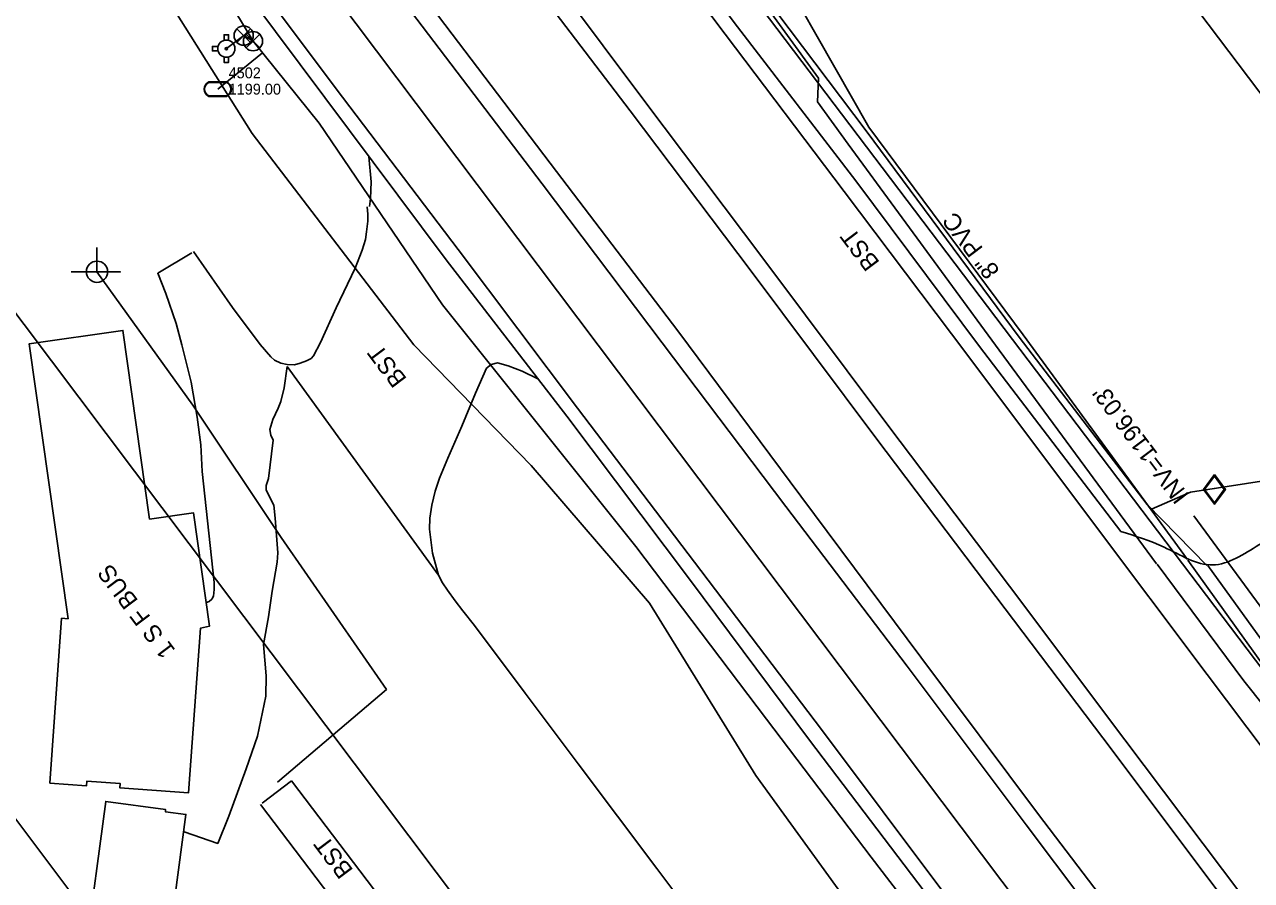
# Model space of a CAD drawing. Extents: x 1262092 to 1264624, y 774970 to 778314.
# Drawn here: x 1262721.5 to 1263004.7, y 777094.1 to 777291.5 of the extents above; entities that cross this region are included whole.
import ezdxf

# ---------------------------------------------------------------- set-up
doc = ezdxf.new("R2010")
doc.units = 0
for name, color, linetype in [('COGO Default Parcel', 7, 'Continuous'), ('Exist Boundary City Limits', 7, 'Continuous'), ('Exist Horizontal Alignment', 7, 'Continuous'), ('Exist Right of Way Line', 7, 'Continuous'), ('Exist Roads Curbs', 7, 'Continuous'), ('Exist Roads EOP', 7, 'Continuous'), ('Exist Roads EOP Other', 7, 'Continuous'), ('Exist Roads EOT', 7, 'Continuous'), ('Exist Structure Minor Pipes CMP 18 Inch', 7, 'Continuous'), ('Exist Structure Minor Pipes CMP 18 Inch Invert', 7, 'Continuous'), ('Exist Utilities Gas UG Line SUE LOS B', 7, 'Continuous'), ('Exist Utilities Gas Valve CELL', 7, 'Continuous'), ('Exist Utilities Power Joint Use Telephone CELL', 7, 'Continuous'), ('Exist Utilities Power UG Cable SUE LOS B', 7, 'Continuous'), ('Exist Utilities Sanitary Sewer UG Line', 7, 'Continuous'), ('Exist Utilities Sanitary Sewer UG Line Text', 7, 'Continuous'), ('Exist Utilities Telephone UG FO SUE LOS B', 7, 'Continuous'), ('Exist Utilities Water Fire Hydrant CELL', 7, 'Continuous'), ('Exist Utilities Water Meter CELL', 7, 'Continuous'), ('Exist Utilities Water Meter Cogo Elevation', 7, 'Continuous'), ('Exist Utilities Water Meter Cogo Number', 7, 'Continuous'), ('Exist Utilities Water UG Line SUE LOS B', 7, 'Continuous'), ('Exist Utilities Water Valve CELL', 7, 'Continuous'), ('Prop EOT', 7, 'Continuous'), ('Prop Horizontal Alignment', 7, 'Continuous'), ('Prop Horizontal Alignment Direction Label', 7, 'Continuous'), ('Prop Horizontal Alignment Tick Small', 7, 'Continuous'), ('Prop Shade Medium', 7, 'Continuous')]:
    doc.layers.add(name, color=color, linetype=linetype)

# ---------------------------------------------------------------- blocks, each defined once
blk = doc.blocks.new('EXIST UTILITIES WATER VALVE')
at = {"layer": 'Exist Utilities Water Valve CELL'}
blk.add_lwpolyline([(0.0315, 0.0315), (-0.0315, -0.0315), (0, 0), (0.0315, -0.0315), (-0.0315, 0.0315)], dxfattribs=at)
blk.add_circle((0, 0), 0.0445, dxfattribs=at)
blk = doc.blocks.new('EXIST UTILITIES WATER FIRE HYDRANT')
at = {"layer": 'Exist Utilities Water Fire Hydrant CELL'}
blk.add_line((0, 0), (0, 0), dxfattribs=at)
for points in [[(-0.01025, 0.03825), (-0.01025, 0.064), (0.01025, 0.064), (0.01025, 0.03775)], [(-0.03825, 0.01025), (-0.064, 0.01025), (-0.064, -0.01025), (-0.03825, -0.01025)], [(-0.01025, -0.03825), (-0.01025, -0.064), (0.01025, -0.064), (0.01025, -0.03775)]]:
    blk.add_lwpolyline(points, dxfattribs=at)
for radius in [0.03954, 0.00485]:
    blk.add_circle((0, 0), radius, dxfattribs=at)
blk = doc.blocks.new('EXIST UTILITIES WATER METER')
at = {"layer": 'Exist Utilities Water Meter CELL'}
blk.add_line((0, 0), (0, 0), dxfattribs=at)
for points in [[(-0.0408, 0.034), (0.0408, 0.034)], [(-0.0408, 0.0312), (0.0408, 0.0312)], [(0.0408, -0.0312), (-0.0413, -0.0312)], [(0.0408, -0.034), (-0.0413, -0.034)]]:
    blk.add_lwpolyline(points, dxfattribs=at)
for centre, radius, start, end in [((-0.0261, -0.0001), 0.0371, 113.178, 245.9794), ((-0.0259, -0.0001), 0.0347, 115.3009, 243.7824), ((0.0259, 0), 0.0371, 293.6483, 66.3084), ((0.0261, 0), 0.0345, 295.1272, 64.8728)]:
    blk.add_arc(centre, radius, start, end, dxfattribs=at)
blk = doc.blocks.new('EXIST UTILITIES GAS VALVE')
at = {"layer": 'Exist Utilities Gas Valve CELL'}
blk.add_line((0, 0), (0, 0), dxfattribs=at)
blk.add_lwpolyline([(0, 0.0683), (-0.0508, 0), (0, -0.0683), (0.0508, 0), (0, 0.0683)], dxfattribs=at)
blk.add_lwpolyline([(0.0458, 0), (0, 0.0615), (-0.0458, 0), (0, -0.0615)], close=True, dxfattribs=at)

msp = doc.modelspace()

# ---------------------------------------------------------------- linework, layer by layer
at = {"layer": 'COGO Default Parcel'}
msp.add_line((1263155.86, 776528.63), (1262121.77, 777902.18), dxfattribs=at)
at = {"layer": 'Exist Boundary City Limits'}
msp.add_line((1263013.39, 776834.66), (1262172.78, 777950.69), dxfattribs=at)
at = {"layer": 'Exist Horizontal Alignment'}
msp.add_line((1264460.35, 775084.79), (1262255.05, 778012.66), dxfattribs=at)
at = {"layer": 'Exist Right of Way Line'}
for p, q in [((1262380.46, 778107.12), (1263428.45, 776715.75)), ((1262172.78, 777950.69), (1263224.83, 776553.94))]:
    msp.add_line(p, q, dxfattribs=at)
at = {"layer": 'Exist Roads Curbs'}
for points in [[(1262760.55, 777239.15), (1262769.56, 777226.25), (1262775.93, 777217.68), (1262778.35, 777214.84), (1262779.26, 777214.07), (1262780.73, 777213.39), (1262782.18, 777213.1), (1262783.83, 777213.03), (1262785.17, 777213.37), (1262786.59, 777213.91), (1262787.69, 777214.47), (1262788.22, 777215.05), (1262789.86, 777218.13), (1262793.5, 777226.13), (1262797.82, 777235.3), (1262799.49, 777239.48), (1262800.23, 777241.93), (1262800.46, 777243.66), (1262800.79, 777246.14), (1262800.77, 777247.76), (1262800.62, 777249.46)], [(1262882.73, 777076.52), (1262867.45, 777096.86), (1262858.42, 777108.9), (1262849.34, 777120.99), (1262837.05, 777137.29), (1262825.37, 777152.88), (1262822.67, 777156.29), (1262820.95, 777158.53), (1262819.14, 777161.01), (1262818, 777162.68), (1262817.1, 777164.49), (1262815.71, 777169.58), (1262815.03, 777175.06), (1262815.09, 777177.66), (1262815.56, 777180.65), (1262816.32, 777183.82), (1262817.34, 777186.88), (1262819.23, 777191.45), (1262822.49, 777198.83), (1262825.63, 777206.45), (1262828.17, 777212.25)]]:
    msp.add_lwpolyline(points, dxfattribs=at)
at = {"layer": 'Exist Roads EOP'}
for p, q in [((1262817.1, 777164.49), (1262782.12, 777212.58)), ((1262776.39, 777111.88), (1262783.19, 777117.01))]:
    msp.add_line(p, q, dxfattribs=at)
for points in [[(1262982.53, 777073.82), (1262955.55, 777109.3), (1262928.42, 777145.56), (1262900.69, 777182.74), (1262872.34, 777220.82), (1262844.32, 777257.6), (1262815.63, 777295.35), (1262787.99, 777332.27), (1262760.77, 777368.27), (1262732.29, 777406.26), (1262703.53, 777444.22), (1262703.55, 777444.2), (1262675.64, 777481.25), (1262647.24, 777519.05), (1262619.25, 777556.57), (1262590.88, 777594.45), (1262562.41, 777631.96), (1262533.86, 777669.85), (1262506.16, 777706.68)], [(1262581.77, 777696.76), (1262605.02, 777665.12), (1262633.36, 777627.24), (1262661.91, 777589.34), (1262690.46, 777551.49), (1262719.22, 777513.4), (1262746.97, 777476.08), (1262773.62, 777440.76), (1262802.75, 777402.21), (1262831.32, 777364.09), (1262858.19, 777328.14), (1262886.09, 777290.94), (1262913.38, 777255.47), (1262941.92, 777217.23), (1262974.58, 777174.56)], [(1262930.86, 777089.4), (1262902.71, 777126.43), (1262875.01, 777163.54), (1262846.68, 777201.15), (1262818.83, 777237.2), (1262790.81, 777274.63), (1262762.38, 777312.81), (1262734.99, 777348.79), (1262707.23, 777385.88), (1262678.03, 777424.58), (1262678.1, 777424.6), (1262649.57, 777462.36), (1262621.56, 777499.63), (1262593.49, 777536.82), (1262564.97, 777574.69), (1262536.79, 777612.19), (1262508.59, 777649.5), (1262480.62, 777686.61)], [(1262551.17, 777683.56), (1262580.06, 777645.73), (1262608.84, 777607.53), (1262637.53, 777569.2), (1262664.94, 777532.66), (1262692.64, 777496.32), (1262720.62, 777458.91), (1262748.48, 777421.14), (1262777.36, 777382.85), (1262804.87, 777346.49), (1262832.58, 777309.22), (1262861.34, 777271.61), (1262889.26, 777234.57), (1262918.02, 777196.13), (1262945.71, 777159.53), (1262972.54, 777124.15), (1262999.26, 777088.5)], [(1262875.07, 776996.05), (1262783.19, 777117.01)], [(1262864.31, 776988.27), (1262843.08, 777016.06), (1262846.56, 777018.7), (1262776, 777111.59)]]:
    msp.add_lwpolyline(points, dxfattribs=at)
msp.add_spline([(1262974.58, 777174.56), (1262984.58, 777170.91), (1262995.75, 777166.84), (1263006.39, 777171.47), (1263014.57, 777176.38)], degree=3, dxfattribs=at)
at = {"layer": 'Exist Roads EOP Other'}
for points in [[(1262801.13, 777249.51), (1262801.38, 777251.38), (1262801.52, 777255.2), (1262800.98, 777261.04)], [(1262772.67, 777119.78), (1262775.32, 777127.37), (1262777.26, 777136.56), (1262777.31, 777141.28), (1262776.73, 777148.5), (1262777.88, 777154.84), (1262778.71, 777160.82), (1262779.83, 777167.49), (1262780.01, 777169.62), (1262779.42, 777177.62), (1262779.1, 777180.6), (1262777.3, 777184.08), (1262777.3, 777185.19), (1262777.82, 777186.81), (1262778.89, 777195.61), (1262778.42, 777196.77), (1262778.13, 777198.05), (1262778.88, 777200.42), (1262780.1, 777202.98), (1262780.71, 777204.54), (1262781.47, 777207.72), (1262782.12, 777212.58)], [(1262828.17, 777212.25), (1262829.24, 777213.08), (1262830.72, 777213.48), (1262833.12, 777212.8), (1262836.39, 777211.57), (1262840.01, 777209.77)], [(1262758.38, 777105.25), (1262766.15, 777102.61), (1262768.7, 777108.9), (1262772.67, 777119.78)]]:
    msp.add_lwpolyline(points, dxfattribs=at)
at = {"layer": 'Exist Roads EOT'}
for points in [[(1262979.34, 777071.55), (1262952.73, 777106.88), (1262925.27, 777143.52), (1262897.25, 777180.33), (1262868.7, 777218.05), (1262841.03, 777254.71), (1262812.09, 777292.76), (1262784.33, 777329.52), (1262756.93, 777366.26), (1262729.04, 777403.83), (1262700.43, 777442.05), (1262700.42, 777442.08), (1262672.68, 777478.81), (1262644.08, 777516.56), (1262615.98, 777553.77), (1262587.41, 777591.99), (1262558.81, 777629.41), (1262530.21, 777667.14), (1262502.53, 777703.54)], [(1262573.92, 777700.82), (1262602.3, 777663.12), (1262630.46, 777625.47), (1262658.86, 777587.71), (1262687.81, 777549.36), (1262715.91, 777512.01), (1262744.26, 777474.24), (1262770.57, 777439.41), (1262799.73, 777400.38), (1262828.22, 777362.56), (1262855.35, 777326.32), (1262883.21, 777289.28), (1262910.68, 777252.94), (1262938.99, 777215.45), (1262967.77, 777177.08), (1262994.46, 777141.54), (1263021.73, 777105.43)], [(1262933.46, 777091.49), (1262905.72, 777128.55), (1262877.63, 777165.57), (1262849.13, 777203), (1262821.64, 777239.58), (1262793.48, 777276.64), (1262765, 777314.68), (1262737.64, 777351.02), (1262709.57, 777388.53), (1262680.86, 777426.61), (1262652.4, 777464.54), (1262624.47, 777501.81), (1262596.33, 777538.99), (1262567.58, 777576.78), (1262539.34, 777614.06), (1262511.28, 777651.42), (1262483.32, 777688.89)], [(1262554.72, 777686.15), (1262583.3, 777648.11), (1262611.88, 777610.15), (1262640.7, 777571.7), (1262668.16, 777535.24), (1262695.77, 777498.64), (1262723.78, 777461.2), (1262751.96, 777423.82), (1262781.01, 777385.34), (1262781, 777385.31), (1262808.32, 777349.17), (1262836.1, 777312), (1262864.5, 777274.02), (1262892.16, 777237.27), (1262921.03, 777198.81), (1262948.88, 777161.95), (1262975.45, 777126.54), (1263002.46, 777090.67)]]:
    msp.add_lwpolyline(points, dxfattribs=at)
at = {"layer": 'Exist Structure Minor Pipes CMP 18 Inch'}
msp.add_line((1263026.59, 777130.21), (1262991.4, 777178.18), dxfattribs=at)
at = {"layer": 'Exist Utilities Gas UG Line SUE LOS B'}
for points in [[(1262994.39, 777166.73), (1262980.63, 777180.77), (1262951.12, 777219.34), (1262915.77, 777266.99), (1262883.3, 777310), (1262857.54, 777344.34), (1262828.14, 777381.91), (1262793.47, 777427.19), (1262760.54, 777472.85), (1262727.33, 777519.3), (1262694.08, 777555.83), (1262655.09, 777608.15), (1262623.1, 777653.3), (1262592.34, 777693.87), (1262575.48, 777722.21), (1262534.9, 777775.61), (1262497.72, 777820.92), (1262460.79, 777868.95), (1262430.33, 777909.82), (1262335.35, 778033.97), (1262366.66, 777994.16), (1262337.19, 778032.97), (1262314.26, 778062.88)], [(1262994.39, 777166.73), (1262980.63, 777180.77), (1262951.12, 777219.34), (1262915.77, 777266.99), (1262883.3, 777310), (1262857.54, 777344.34), (1262828.14, 777381.91), (1262793.47, 777427.19), (1262760.54, 777472.85), (1262727.33, 777519.3), (1262694.08, 777555.83), (1262655.09, 777608.15), (1262623.1, 777653.3), (1262592.34, 777693.87), (1262575.48, 777722.21), (1262534.9, 777775.61), (1262497.72, 777820.92), (1262460.79, 777868.95), (1262430.33, 777909.82), (1262335.35, 778033.97), (1262366.66, 777994.16), (1262337.19, 778032.97), (1262314.26, 778062.88)], [(1262981.64, 777179.74), (1262990.66, 777183.59), (1263010.03, 777186.59), (1263023.13, 777192.41), (1263060.72, 777217.64), (1263088.74, 777237.85)], [(1262981.64, 777179.74), (1262990.66, 777183.59), (1263010.03, 777186.59), (1263023.13, 777192.41), (1263060.72, 777217.64), (1263088.74, 777237.85)], [(1263356.42, 776704.29), (1263329.58, 776735.35), (1263277.38, 776797.97), (1263260.37, 776819.29), (1263232.35, 776857.44), (1263174.41, 776935.65), (1263134.72, 776985.69), (1263099.47, 777025.86), (1263058.51, 777081.95), (1263034.87, 777111.45), (1263010.04, 777145.44), (1262994.6, 777166.7)], [(1263356.42, 776704.29), (1263329.58, 776735.35), (1263277.38, 776797.97), (1263260.37, 776819.29), (1263232.35, 776857.44), (1263174.41, 776935.65), (1263134.72, 776985.69), (1263099.47, 777025.86), (1263058.51, 777081.95), (1263034.87, 777111.45), (1263010.04, 777145.44), (1262994.6, 777166.7)]]:
    msp.add_lwpolyline(points, dxfattribs=at)
at = {"layer": 'Exist Utilities Power Joint Use Telephone CELL'}
msp.add_line((1262738.26, 777234.45), (1262738.26, 777234.45), dxfattribs=at)
msp.add_lwpolyline([(1262732.32, 777234.45), (1262743.66, 777234.42), (1262738.26, 777234.43), (1262738.26, 777240.08)], dxfattribs=at)
msp.add_circle((1262738.26, 777234.46), 2.45, dxfattribs=at)
at = {"layer": 'Exist Utilities Power UG Cable SUE LOS B'}
msp.add_lwpolyline([(1262779.96, 777116.73), (1262805.07, 777138.14), (1262780.75, 777173.2), (1262760.4, 777203.7), (1262738.26, 777234.45)], dxfattribs=at)
at = {"layer": 'Exist Utilities Sanitary Sewer UG Line'}
msp.add_line((1263142.14, 776964.69), (1262537.27, 777762.91), dxfattribs=at)
at = {"layer": 'Exist Utilities Telephone UG FO SUE LOS B'}
for points in [[(1262989.94, 777168.07), (1262951.99, 777219.94), (1262916.42, 777267.81), (1262888.77, 777316.31), (1262864.92, 777351.47), (1262838.91, 777387.68), (1262799.61, 777432.02), (1262765.27, 777476.73), (1262731.32, 777522.28), (1262700.44, 777560.94), (1262661.97, 777612.3), (1262627.92, 777657.64), (1262612.11, 777680.33), (1262604.08, 777687.9), (1262594.67, 777695.7), (1262574.71, 777722.66), (1262534.65, 777775.25), (1262499.34, 777822.06), (1262462.07, 777869.42), (1262431.13, 777910.63), (1262336.58, 778034.92), (1262368.35, 777994.88), (1262338.32, 778033.37), (1262315.72, 778063.86)], [(1262989.94, 777168.07), (1262951.99, 777219.94), (1262916.42, 777267.81), (1262888.77, 777316.31), (1262864.92, 777351.47), (1262838.91, 777387.68), (1262799.61, 777432.02), (1262765.27, 777476.73), (1262731.32, 777522.28), (1262700.44, 777560.94), (1262661.97, 777612.3), (1262627.92, 777657.64), (1262612.11, 777680.33), (1262604.08, 777687.9), (1262594.67, 777695.7), (1262574.71, 777722.66), (1262534.65, 777775.25), (1262499.34, 777822.06), (1262462.07, 777869.42), (1262431.13, 777910.63), (1262336.58, 778034.92), (1262368.35, 777994.88), (1262338.32, 778033.37), (1262315.72, 778063.86)], [(1262982.78, 777167.11), (1262946.46, 777216.4), (1262911.63, 777263.89), (1262904.55, 777273.66), (1262904.75, 777279.08), (1262882.68, 777309.56), (1262855.72, 777342.59), (1262826.17, 777380.64), (1262792.14, 777426.47), (1262758.72, 777471.04), (1262724.36, 777517.1), (1262692.7, 777554.83), (1262654.13, 777607.32), (1262621.89, 777651.43), (1262589.79, 777691.14), (1262572.86, 777709.66), (1262527.82, 777770.05), (1262493.25, 777818.33), (1262456.6, 777866.38), (1262426.24, 777906.46), (1262391.81, 777952.18), (1262362.73, 777991.03), (1262332.92, 778030.12), (1262309.95, 778059.98)], [(1262910.35, 777090.71), (1262890.34, 777118.27), (1262865.78, 777158.05), (1262838.45, 777189.77), (1262811.38, 777217.63), (1262774.04, 777266.39), (1262739.96, 777320.46), (1262735.6, 777333.52), (1262715.57, 777355.48), (1262686.67, 777396.44), (1262655.65, 777437.37), (1262635.3, 777465.04), (1262584.48, 777532.7), (1262553.29, 777574), (1262535.57, 777596.2), (1262497.69, 777644.72), (1262472.81, 777678.82)], [(1263373.48, 776676.85), (1263365.2, 776684.82), (1263352.59, 776693.87), (1263341.76, 776702.87), (1263321.04, 776726.71), (1263286.07, 776766.71), (1263269.2, 776787.89), (1263249.18, 776814.48), (1263222.87, 776850.05), (1263191.25, 776891.88), (1263163.23, 776928.72), (1263125.76, 776977.57), (1263092.62, 777021.21), (1263050.93, 777076.69), (1263030.47, 777105.6), (1263002.91, 777140.08), (1262982.96, 777166.99)], [(1263374.12, 776677.22), (1263367.54, 776687.65), (1263357.01, 776697.23), (1263347.13, 776706.88), (1263325.91, 776730.33), (1263290.3, 776770.26), (1263273.49, 776792.41), (1263254.57, 776818.08), (1263227.55, 776854.35), (1263196.01, 776895.13), (1263202.16, 776898.58), (1263168.11, 776933.04), (1263131.19, 776983.12), (1263097.32, 777024.45), (1263055.61, 777080.3), (1263033.94, 777109.7), (1263007.65, 777143.42), (1262989.99, 777167.92)]]:
    msp.add_lwpolyline(points, dxfattribs=at)
at = {"layer": 'Exist Utilities Water UG Line SUE LOS B'}
msp.add_line((1262776.48, 777284.93), (1262766.14, 777276.57), dxfattribs=at)
for points in [[(1262961.53, 777041.32), (1262916.91, 777099.45), (1262892.75, 777131.3), (1262862.6, 777171.1), (1262817.98, 777226.85), (1262789.55, 777268.74), (1262774.27, 777287.66), (1262763.83, 777305.05), (1262732.33, 777346.94), (1262685.88, 777410.11), (1262660.87, 777443.18), (1262632.31, 777481.08), (1262598.3, 777526.4), (1262560.14, 777576.52), (1262506.51, 777647.45), (1262479.01, 777683.48), (1262453.07, 777718.25), (1262416.94, 777766.02), (1262382.77, 777811.78), (1262358.61, 777844.73), (1262327.38, 777885.68), (1262302.32, 777918.54), (1262259.45, 777971.43), (1262223.66, 778020.3)], [(1262774.27, 777287.66), (1262772.12, 777288.94), (1262768.12, 777285.93)]]:
    msp.add_lwpolyline(points, dxfattribs=at)
at = {"layer": 'Prop Horizontal Alignment Direction Label'}
msp.add_lwpolyline([(1262728.57, 777029.53), (1262747.81, 776910.15), (1262761.37, 776912.27), (1262755.63, 776948.52), (1262742.52, 777028.97), (1262749.97, 777081.77), (1262751.82, 777081.6), (1262752.69, 777088.08), (1262753.03, 777090.55), (1262756.22, 777090.12), (1262758.8, 777109.29), (1262754.04, 777109.93), (1262754.11, 777110.42), (1262740.29, 777112.28), (1262735.6, 777077.34), (1262734.99, 777077.42)], close=True, dxfattribs=at)
at = {"layer": 'Prop Horizontal Alignment Tick Small'}
msp.add_lwpolyline([(1262763.55, 777158.15), (1262764.15, 777158.42), (1262764.75, 777158.92), (1262765.16, 777159.67), (1262765.33, 777161.16), (1262765.28, 777162.76), (1262762.55, 777188.36), (1262762.26, 777194.55), (1262761.36, 777200.96), (1262759.98, 777209.03), (1262757.88, 777217.63), (1262756.53, 777222.51), (1262754.15, 777229.48), (1262752.27, 777234.13), (1262760.12, 777238.85)], dxfattribs=at)
at = {"layer": 'Prop Shade Medium'}
msp.add_lwpolyline([(1262731.64, 777154.44), (1262730.11, 777154.55), (1262727.41, 777116.51), (1262735.85, 777115.9), (1262735.93, 777116.98), (1262743.63, 777116.42), (1262743.56, 777115.43), (1262759.35, 777114.24), (1262762.19, 777152.27), (1262764.22, 777152.71), (1262760.51, 777178.86), (1262750.42, 777177.43), (1262744.26, 777220.94), (1262722.65, 777217.87)], close=True, dxfattribs=at)

# ---------------------------------------------------------------- block references
at = {"layer": 'Exist Utilities Gas Valve CELL', "xscale": 50, "yscale": 50}
msp.add_blockref('EXIST UTILITIES GAS VALVE', (1262996.14, 777184.25), dxfattribs=at)
at = {"layer": 'Exist Utilities Water Fire Hydrant CELL', "xscale": 50, "yscale": 50}
msp.add_blockref('EXIST UTILITIES WATER FIRE HYDRANT', (1262768.12, 777285.93), dxfattribs=at)
at = {"layer": 'Exist Utilities Water Meter CELL', "xscale": 50, "yscale": 50}
msp.add_blockref('EXIST UTILITIES WATER METER', (1262766.14, 777276.57), dxfattribs=at)
at = {"layer": 'Exist Utilities Water Valve CELL', "xscale": 50, "yscale": 50}
for p in [(1262772.12, 777288.94), (1262774.27, 777287.66)]:
    msp.add_blockref('EXIST UTILITIES WATER VALVE', p, dxfattribs=at)

# ---------------------------------------------------------------- texts
at = {"layer": 'Exist Structure Minor Pipes CMP 18 Inch Invert'}
msp.add_text("INV=1196.03'", height=4, rotation=126.9874, dxfattribs=at).set_placement((1262990.45, 777182.88))
at = {"layer": 'Exist Utilities Sanitary Sewer UG Line Text'}
msp.add_text('8" PVC', height=4, rotation=127.1538, dxfattribs=at).set_placement((1262946.75, 777234.74))
at = {"layer": 'Exist Utilities Water Meter Cogo Elevation'}
msp.add_text('1199.00', height=2.5, dxfattribs=at).set_placement((1262768.64, 777275.33))
at = {"layer": 'Exist Utilities Water Meter Cogo Number'}
msp.add_text('4502', height=2.5, dxfattribs=at).set_placement((1262768.64, 777279.08))
at = {"layer": 'Prop EOT'}
msp.add_text('1 S F BUS', height=4, rotation=126.9874, dxfattribs=at).set_placement((1262756.5, 777147.18))
at = {"layer": 'Prop Horizontal Alignment'}
for p in [(1262919.03, 777236.6), (1262919.03, 777236.6), (1262809.92, 777209.74), (1262797.53, 777096.44)]:
    msp.add_text('BST', height=4, rotation=126.9874, dxfattribs=at).set_placement(p)

doc.saveas('drawing.dxf')
